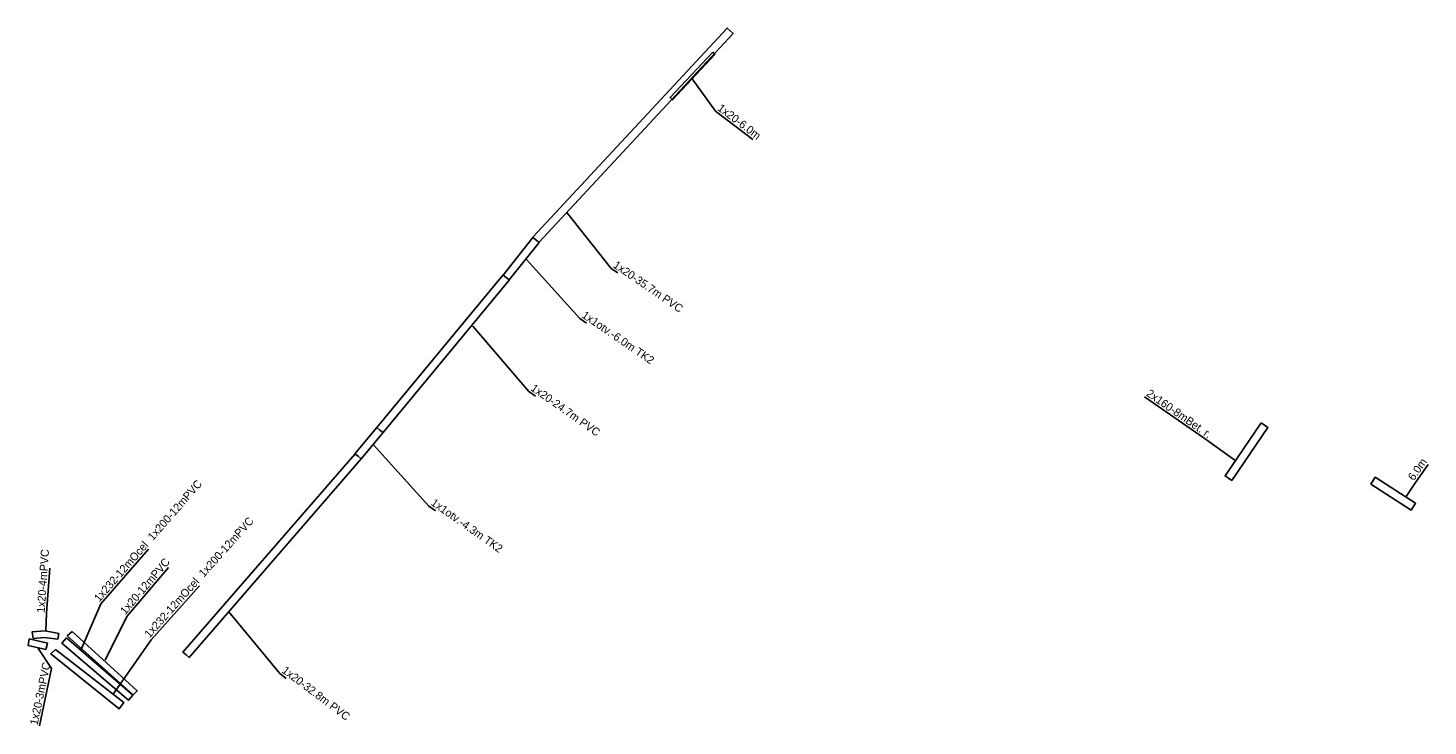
# Model space of a CAD drawing. Extents: x -742805 to -742630, y -1054562 to -1054474.
import ezdxf

# ---------------------------------------------------------------- set-up
doc = ezdxf.new("R2010")
doc.units = 0
doc.layers.add('Chránička', color=7, linetype='Continuous')
doc.layers.add('ST_CHRANICKA_POPIS', color=7, linetype='Continuous')

msp = doc.modelspace()

# ---------------------------------------------------------------- linework, layer by layer
at = {"layer": 'Chránička'}
for points in [[(-742741.076, -1054500.818), (-742741.442, -1054500.478), (-742717.177, -1054474.354), (-742716.811, -1054474.694), (-742716.445, -1054475.034), (-742740.71, -1054501.158), (-742741.076, -1054500.818)], [(-742718.986, -1054477.354), (-742718.694, -1054477.627), (-742723.988, -1054483.328), (-742724.317, -1054483.049), (-742718.986, -1054477.354)], [(-742744.796, -1054505.51), (-742745.188, -1054505.199), (-742741.468, -1054500.507), (-742741.076, -1054500.818), (-742740.684, -1054501.129), (-742744.404, -1054505.821), (-742744.796, -1054505.51)], [(-742760.56, -1054524.566), (-742760.945, -1054524.247), (-742745.181, -1054505.191), (-742744.796, -1054505.51), (-742744.411, -1054505.829), (-742760.175, -1054524.885), (-742760.56, -1054524.566)], [(-742763.301, -1054527.843), (-742763.685, -1054527.522), (-742760.944, -1054524.245), (-742760.56, -1054524.566), (-742760.176, -1054524.887), (-742762.917, -1054528.164), (-742763.301, -1054527.843)], [(-742650.459, -1054523.675), (-742649.631, -1054524.237), (-742654.126, -1054530.855), (-742654.954, -1054530.293), (-742650.459, -1054523.675)], [(-742784.797, -1054552.643), (-742785.175, -1054552.316), (-742763.679, -1054527.516), (-742763.301, -1054527.843), (-742762.923, -1054528.17), (-742784.419, -1054552.97), (-742784.797, -1054552.643)], [(-742636.736, -1054531.306), (-742636.196, -1054530.464), (-742631.149, -1054533.709), (-742631.689, -1054534.551), (-742636.736, -1054531.306)], [(-742804.406, -1054550.63), (-742802.096, -1054551.17), (-742802.316, -1054551.949), (-742804.542, -1054551.464), (-742804.406, -1054550.63)], [(-742803.913, -1054550.593), (-742804.041, -1054549.779), (-742802.401, -1054549.643), (-742800.691, -1054549.987), (-742800.815, -1054550.69), (-742802.509, -1054550.448), (-742803.913, -1054550.593)], [(-742799.743, -1054550.51), (-742791.433, -1054557.66), (-742791.99, -1054558.299), (-742800.305, -1054551.156), (-742799.743, -1054550.51)], [(-742799.042, -1054549.71), (-742790.892, -1054557.15), (-742791.404, -1054557.639), (-742799.646, -1054550.24), (-742799.042, -1054549.71)], [(-742801.106, -1054551.949), (-742792.587, -1054558.58), (-742793.141, -1054559.359), (-742801.701, -1054552.509), (-742801.106, -1054551.949)]]:
    msp.add_lwpolyline(points, close=True, dxfattribs=at)
at = {"layer": 'ST_CHRANICKA_POPIS'}
for points in [[(-742721.536, -1054480.686), (-742718.624, -1054484.732), (-742713.985, -1054488.269)], [(-742737.229, -1054497.383), (-742731.666, -1054504.382), (-742730.842, -1054504.948)], [(-742742.267, -1054503.247), (-742735.582, -1054510.634), (-742734.758, -1054511.201)], [(-742748.951, -1054511.593), (-742741.959, -1054519.736), (-742741.142, -1054520.313)], [(-742665.027, -1054520.418), (-742657.592, -1054525.593), (-742653.736, -1054528.32)], [(-742761.391, -1054526.383), (-742754.436, -1054534.056), (-742753.619, -1054534.633)], [(-742632.339, -1054532.857), (-742631.167, -1054531.105), (-742629.604, -1054528.848)], [(-742797.921, -1054552.068), (-742795.451, -1054546.267), (-742789.486, -1054539.449)], [(-742802.318, -1054549.637), (-742802.216, -1054547.433), (-742801.827, -1054541.819)], [(-742794.916, -1054553.317), (-742792.188, -1054547.858), (-742786.982, -1054541.745)], [(-742793.892, -1054557.562), (-742789.169, -1054550.764), (-742783.128, -1054544.013)], [(-742779.446, -1054547.265), (-742773.062, -1054554.969), (-742772.264, -1054555.571)], [(-742803.102, -1054561.519), (-742801.601, -1054554.332), (-742803.329, -1054551.75)]]:
    msp.add_lwpolyline(points, dxfattribs=at)

# ---------------------------------------------------------------- texts
for s, rotation, p in [('1x20-6.0m', 322.67499, (-742718.473, -1054484.534)), ('1x20-35.7m PVC', 325.51342, (-742731.524, -1054504.176)), ('1x1otv.-6.0m TK2', 325.51435, (-742735.44, -1054510.428)), ('1x20-24.7m PVC', 324.77535, (-742741.815, -1054519.532)), ('2x160-8mBet. r.', 325.15672, (-742664.884, -1054520.213)), ('6.0m', 55.2914, (-742631.373, -1054530.963)), ('1x232-12mOcel  1x200-12mPVC', 48.81764, (-742795.639, -1054546.102)), ('1x1otv.-4.3m TK2', 324.77535, (-742754.292, -1054533.852)), ('1x232-12mOcel  1x200-12mPVC', 48.17468, (-742789.356, -1054550.597)), ('1x20-4mPVC', 86.03456, (-742802.466, -1054547.416)), ('1x20-12mPVC', 49.57605, (-742792.379, -1054547.696)), ('1x20-3mPVC', 78.20352, (-742803.346, -1054561.468)), ('1x20-32.8m PVC', 322.94604, (-742772.912, -1054554.769))]:
    msp.add_text(s, height=1, rotation=rotation, dxfattribs=at).set_placement(p)

doc.saveas('drawing.dxf')
